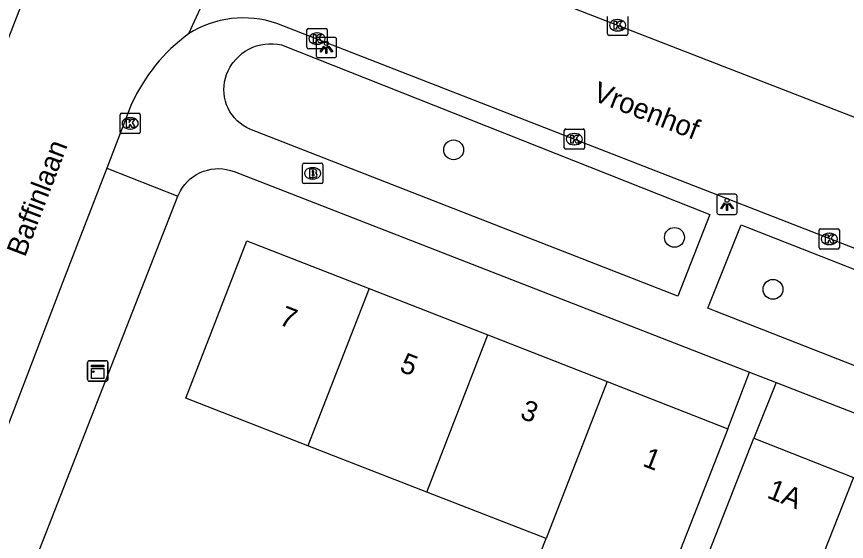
# Model space of a CAD drawing. Extents: x 161253 to 161848, y 384872 to 385383.
# Drawn here: x 161608.6 to 161649.49, y 385097.58 to 385123.42 of the extents above; entities that cross this region are included whole.
import ezdxf

# ---------------------------------------------------------------- set-up
doc = ezdxf.new("R2010")
doc.units = 0
for name, color, linetype in [('IMGEO_Boom', 7, 'Continuous'), ('IMGEO_Brandkraan', 7, 'Continuous'), ('IMGEO_Kast', 7, 'Continuous'), ('IMGEO_Kolk', 7, 'Continuous'), ('IMGEO_Lichtpunt', 7, 'Continuous'), ('IMGEO_Openbare_ruimte_label', 7, 'Continuous'), ('IMGEO_Pand', 7, 'Continuous'), ('IMGEO_Pand_nummerreeks', 7, 'Continuous'), ('IMGEO_Rijbaan_lokaal_open', 7, 'Continuous'), ('IMGEO_Voetpad_open', 7, 'Continuous')]:
    doc.layers.add(name, color=color, linetype=linetype)

msp = doc.modelspace()

# ---------------------------------------------------------------- linework, layer by layer
at = {"layer": 'IMGEO_Boom'}
for centre in [(161630.137, 385116.861), (161641.02, 385112.549), (161645.875, 385109.992)]:
    msp.add_circle(centre, 0.489, dxfattribs=at)
at = {"layer": 'IMGEO_Brandkraan'}
for p, q in [((161622.764, 385116.202), (161623.616, 385116.202)), ((161622.689, 385115.276), (161622.689, 385116.128)), ((161623.177, 385115.982), (161623.202, 385115.982)), ((161623.69, 385116.128), (161623.69, 385115.276)), ((161623.2, 385115.422), (161623.175, 385115.422)), ((161623.616, 385115.202), (161622.764, 385115.202))]:
    msp.add_line(p, q, dxfattribs=at)
for points in [[(161622.764, 385116.202), (161623.616, 385116.202)], [(161622.689, 385115.276), (161622.689, 385116.128)], [(161623.037, 385115.902), (161623.037, 385115.502), (161623.25, 385115.502)], [(161623.268, 385115.902), (161623.037, 385115.902)], [(161623.216, 385115.821), (161623.162, 385115.821), (161623.162, 385115.745)], [(161623.69, 385116.128), (161623.69, 385115.276)], [(161623.162, 385115.745), (161623.215, 385115.745)], [(161623.224, 385115.669), (161623.162, 385115.669), (161623.162, 385115.588)], [(161623.162, 385115.588), (161623.224, 385115.588)], [(161623.616, 385115.202), (161622.764, 385115.202)]]:
    msp.add_lwpolyline(points, dxfattribs=at)
for centre, radius, start, end in [((161622.766, 385116.126), 0.0765, 91.552, 178.448), ((161622.766, 385116.126), 0.0765, 91.552, 178.448), ((161623.614, 385116.126), 0.0765, 1.552, 88.448), ((161623.614, 385116.126), 0.0765, 1.552, 88.448), ((161623.217, 385115.783), 0.0379, 267.8285, 90.9355), ((161623.272, 385115.757), 0.145, 59.4692, 91.5367), ((161623.297, 385115.804), 0.0922, 285.5137, 58.1501), ((161623.225, 385115.628), 0.0404, 269.8759, 90.5077), ((161623.256, 385115.753), 0.251, 268.6676, 293.5347), ((161623.302, 385115.612), 0.105, 301.3115, 78.989), ((161622.766, 385115.278), 0.0765, 181.552, 268.448), ((161622.766, 385115.278), 0.0765, 181.552, 268.448), ((161623.614, 385115.278), 0.0765, 271.552, 358.448), ((161623.614, 385115.278), 0.0765, 271.552, 358.448)]:
    msp.add_arc(centre, radius, start, end, dxfattribs=at)
for centre, major_axis, ratio, start_param, end_param in [((161623.176, 385115.702), (-0.387, 0.002), 0.722429, 4.712389, 7.853982), ((161623.201, 385115.702), (-0.39, 0.002), 0.717154, 1.570796, 4.712389)]:
    msp.add_ellipse(centre, major_axis=major_axis, ratio=ratio, start_param=start_param, end_param=end_param, dxfattribs=at)
at = {"layer": 'IMGEO_Kast'}
for p, q in [((161612.097, 385105.546), (161612.097, 385106.387)), ((161612.097, 385106.387), (161612.097, 385105.546)), ((161612.172, 385106.471), (161613.013, 385106.471)), ((161613.013, 385106.471), (161612.172, 385106.471)), ((161613.097, 385106.396), (161613.097, 385105.555)), ((161613.097, 385105.555), (161613.097, 385106.396)), ((161613.022, 385105.471), (161612.181, 385105.471)), ((161612.181, 385105.471), (161613.022, 385105.471))]:
    msp.add_line(p, q, dxfattribs=at)
for points in [[(161612.292, 385106.261), (161612.892, 385106.261), (161612.892, 385106.176), (161612.292, 385106.176), (161612.292, 385106.261)], [(161612.292, 385106.086), (161612.892, 385106.086), (161612.892, 385105.597), (161612.292, 385105.597), (161612.292, 385106.086)]]:
    msp.add_lwpolyline(points, dxfattribs=at)
msp.add_circle((161612.376, 385105.935), 0.0377, dxfattribs=at)
for centre, start, end in [((161612.175, 385106.393), 92.4484, 184.2845), ((161612.175, 385106.393), 92.4484, 184.2845), ((161613.019, 385106.393), 2.4484, 94.2845), ((161613.019, 385106.393), 2.4484, 94.2845), ((161613.019, 385105.549), 272.4484, 4.2845), ((161613.019, 385105.549), 272.4484, 4.2845), ((161612.175, 385105.549), 182.4484, 274.2845), ((161612.175, 385105.549), 182.4484, 274.2845)]:
    msp.add_arc(centre, 0.0779, start, end, dxfattribs=at)
at = {"layer": 'IMGEO_Kolk'}
for p, q in [((161637.72, 385122.568), (161637.72, 385123.42)), ((161638.208, 385123.274), (161638.233, 385123.274)), ((161638.721, 385123.42), (161638.721, 385122.568)), ((161622.907, 385121.91), (161622.907, 385122.762)), ((161622.982, 385122.836), (161623.834, 385122.836)), ((161623.908, 385122.762), (161623.908, 385121.91)), ((161623.395, 385122.616), (161623.42, 385122.616)), ((161638.647, 385122.494), (161637.795, 385122.494)), ((161638.231, 385122.714), (161638.206, 385122.714)), ((161623.418, 385122.056), (161623.393, 385122.056)), ((161623.834, 385121.836), (161622.982, 385121.836)), ((161613.77, 385118.663), (161614.622, 385118.663)), ((161613.695, 385117.737), (161613.695, 385118.589)), ((161614.183, 385118.443), (161614.208, 385118.443)), ((161614.696, 385118.589), (161614.696, 385117.737)), ((161614.206, 385117.883), (161614.181, 385117.883)), ((161635.662, 385117.886), (161636.514, 385117.886)), ((161614.622, 385117.663), (161613.77, 385117.663)), ((161635.587, 385116.96), (161635.587, 385117.812)), ((161636.075, 385117.666), (161636.1, 385117.666)), ((161636.588, 385117.812), (161636.588, 385116.96)), ((161636.098, 385117.106), (161636.073, 385117.106)), ((161636.514, 385116.886), (161635.662, 385116.886)), ((161648.224, 385112.973), (161649.076, 385112.973)), ((161648.149, 385112.047), (161648.149, 385112.899)), ((161648.637, 385112.753), (161648.662, 385112.753)), ((161649.15, 385112.899), (161649.15, 385112.047)), ((161648.66, 385112.193), (161648.635, 385112.193)), ((161649.076, 385111.973), (161648.224, 385111.973))]:
    msp.add_line(p, q, dxfattribs=at)
for points in [[(161637.72, 385122.568), (161637.72, 385123.42)], [(161638.041, 385123.194), (161638.164, 385123.194), (161638.164, 385123.043), (161638.294, 385123.194), (161638.458, 385123.194), (161638.312, 385123.043), (161638.465, 385122.794), (161638.313, 385122.794), (161638.228, 385122.958), (161638.164, 385122.891), (161638.164, 385122.794), (161638.041, 385122.794), (161638.041, 385123.194)], [(161638.721, 385123.42), (161638.721, 385122.568)], [(161622.907, 385121.91), (161622.907, 385122.762)], [(161622.982, 385122.836), (161623.834, 385122.836)], [(161623.908, 385122.762), (161623.908, 385121.91)], [(161623.228, 385122.536), (161623.351, 385122.536), (161623.351, 385122.385), (161623.481, 385122.536), (161623.645, 385122.536), (161623.499, 385122.385), (161623.652, 385122.136), (161623.5, 385122.136), (161623.415, 385122.3), (161623.351, 385122.233), (161623.351, 385122.136), (161623.228, 385122.136), (161623.228, 385122.536)], [(161638.647, 385122.494), (161637.795, 385122.494)], [(161623.834, 385121.836), (161622.982, 385121.836)], [(161613.77, 385118.663), (161614.622, 385118.663)], [(161613.695, 385117.737), (161613.695, 385118.589)], [(161614.016, 385118.363), (161614.139, 385118.363), (161614.139, 385118.212), (161614.269, 385118.363), (161614.433, 385118.363), (161614.287, 385118.212), (161614.44, 385117.963), (161614.288, 385117.963), (161614.203, 385118.127), (161614.139, 385118.06), (161614.139, 385117.963), (161614.016, 385117.963), (161614.016, 385118.363)], [(161614.696, 385118.589), (161614.696, 385117.737)], [(161635.662, 385117.886), (161636.514, 385117.886)], [(161614.622, 385117.663), (161613.77, 385117.663)], [(161635.587, 385116.96), (161635.587, 385117.812)], [(161635.908, 385117.586), (161636.031, 385117.586), (161636.031, 385117.435), (161636.161, 385117.586), (161636.325, 385117.586), (161636.179, 385117.435), (161636.332, 385117.186), (161636.18, 385117.186), (161636.095, 385117.35), (161636.031, 385117.283), (161636.031, 385117.186), (161635.908, 385117.186), (161635.908, 385117.586)], [(161636.588, 385117.812), (161636.588, 385116.96)], [(161636.514, 385116.886), (161635.662, 385116.886)], [(161648.224, 385112.973), (161649.076, 385112.973)], [(161648.149, 385112.047), (161648.149, 385112.899)], [(161648.47, 385112.673), (161648.593, 385112.673), (161648.593, 385112.522), (161648.723, 385112.673), (161648.887, 385112.673), (161648.741, 385112.522), (161648.894, 385112.273), (161648.742, 385112.273), (161648.657, 385112.437), (161648.593, 385112.37), (161648.593, 385112.273), (161648.47, 385112.273), (161648.47, 385112.673)], [(161649.15, 385112.899), (161649.15, 385112.047)], [(161649.076, 385111.973), (161648.224, 385111.973)]]:
    msp.add_lwpolyline(points, dxfattribs=at)
for centre, start, end in [((161622.984, 385122.76), 91.552, 178.448), ((161622.984, 385122.76), 91.552, 178.448), ((161623.832, 385122.76), 1.552, 88.448), ((161623.832, 385122.76), 1.552, 88.448), ((161637.797, 385122.57), 181.552, 268.448), ((161637.797, 385122.57), 181.552, 268.448), ((161638.645, 385122.57), 271.552, 358.448), ((161638.645, 385122.57), 271.552, 358.448), ((161622.984, 385121.912), 181.552, 268.448), ((161622.984, 385121.912), 181.552, 268.448), ((161623.832, 385121.912), 271.552, 358.448), ((161623.832, 385121.912), 271.552, 358.448), ((161613.772, 385118.587), 91.552, 178.448), ((161613.772, 385118.587), 91.552, 178.448), ((161614.62, 385118.587), 1.552, 88.448), ((161614.62, 385118.587), 1.552, 88.448), ((161635.664, 385117.81), 91.552, 178.448), ((161635.664, 385117.81), 91.552, 178.448), ((161636.512, 385117.81), 1.552, 88.448), ((161636.512, 385117.81), 1.552, 88.448), ((161613.772, 385117.739), 181.552, 268.448), ((161613.772, 385117.739), 181.552, 268.448), ((161614.62, 385117.739), 271.552, 358.448), ((161614.62, 385117.739), 271.552, 358.448), ((161635.664, 385116.962), 181.552, 268.448), ((161635.664, 385116.962), 181.552, 268.448), ((161636.512, 385116.962), 271.552, 358.448), ((161636.512, 385116.962), 271.552, 358.448), ((161648.226, 385112.897), 91.552, 178.448), ((161648.226, 385112.897), 91.552, 178.448), ((161649.074, 385112.897), 1.552, 88.448), ((161649.074, 385112.897), 1.552, 88.448), ((161648.226, 385112.049), 181.552, 268.448), ((161648.226, 385112.049), 181.552, 268.448), ((161649.074, 385112.049), 271.552, 358.448), ((161649.074, 385112.049), 271.552, 358.448)]:
    msp.add_arc(centre, 0.0765, start, end, dxfattribs=at)
for centre, major_axis, ratio, start_param, end_param in [((161638.207, 385122.994), (-0.387, 0.002), 0.722429, 4.712389, 7.853982), ((161638.232, 385122.994), (-0.39, 0.002), 0.717154, 1.570796, 4.712389), ((161623.394, 385122.336), (-0.387, 0.002), 0.722429, 4.712389, 7.853982), ((161623.419, 385122.336), (-0.39, 0.002), 0.717154, 1.570796, 4.712389), ((161614.182, 385118.163), (-0.387, 0.002), 0.722429, 4.712389, 7.853982), ((161614.207, 385118.163), (-0.39, 0.002), 0.717154, 1.570796, 4.712389), ((161636.074, 385117.386), (-0.387, 0.002), 0.722429, 4.712389, 7.853982), ((161636.099, 385117.386), (-0.39, 0.002), 0.717154, 1.570796, 4.712389), ((161648.636, 385112.473), (-0.387, 0.002), 0.722429, 4.712389, 7.853982), ((161648.661, 385112.473), (-0.39, 0.002), 0.717154, 1.570796, 4.712389)]:
    msp.add_ellipse(centre, major_axis=major_axis, ratio=ratio, start_param=start_param, end_param=end_param, dxfattribs=at)
at = {"layer": 'IMGEO_Lichtpunt'}
for p, q in [((161624.269, 385122.398), (161623.461, 385122.398)), ((161624.269, 385122.398), (161623.461, 385122.398)), ((161623.367, 385122.303), (161623.367, 385121.496)), ((161623.367, 385122.303), (161623.367, 385121.496)), ((161624.363, 385121.496), (161624.363, 385122.303)), ((161624.363, 385121.496), (161624.363, 385122.303)), ((161623.461, 385121.402), (161624.269, 385121.402)), ((161623.461, 385121.402), (161624.269, 385121.402)), ((161643.112, 385114.579), (161643.112, 385113.772)), ((161643.112, 385114.579), (161643.112, 385113.772)), ((161644.014, 385114.674), (161643.206, 385114.674)), ((161644.014, 385114.674), (161643.206, 385114.674)), ((161644.108, 385113.772), (161644.108, 385114.579)), ((161644.108, 385113.772), (161644.108, 385114.579)), ((161643.206, 385113.678), (161644.014, 385113.678)), ((161643.206, 385113.678), (161644.014, 385113.678))]:
    msp.add_line(p, q, dxfattribs=at)
for points in [[(161623.741, 385121.967), (161623.78, 385121.939), (161623.592, 385121.677), (161623.554, 385121.704), (161623.741, 385121.967)], [(161623.843, 385121.919), (161623.89, 385121.919), (161623.89, 385121.597), (161623.843, 385121.597), (161623.843, 385121.919)], [(161623.953, 385121.939), (161623.991, 385121.966), (161624.178, 385121.704), (161624.139, 385121.676), (161623.953, 385121.939)], [(161643.486, 385114.243), (161643.525, 385114.215), (161643.337, 385113.953), (161643.299, 385113.98), (161643.486, 385114.243)], [(161643.588, 385114.195), (161643.635, 385114.195), (161643.635, 385113.873), (161643.588, 385113.873), (161643.588, 385114.195)], [(161643.698, 385114.215), (161643.736, 385114.242), (161643.923, 385113.98), (161643.884, 385113.952), (161643.698, 385114.215)]]:
    msp.add_lwpolyline(points, dxfattribs=at)
for centre in [(161623.866, 385122.101), (161643.611, 385114.377)]:
    msp.add_circle(centre, 0.0994, dxfattribs=at)
for centre, start, end in [((161623.461, 385122.303), 90, 180), ((161623.461, 385122.303), 90, 180), ((161624.269, 385122.303), 0, 90), ((161624.269, 385122.303), 0, 90), ((161623.461, 385121.496), 180, 270), ((161623.461, 385121.496), 180, 270), ((161624.269, 385121.496), 270, 0), ((161624.269, 385121.496), 270, 360), ((161643.206, 385114.579), 90, 180), ((161643.206, 385114.579), 90, 180), ((161644.014, 385114.579), 0, 90), ((161644.014, 385114.579), 0, 90), ((161643.206, 385113.772), 180, 270), ((161643.206, 385113.772), 180, 270), ((161644.014, 385113.772), 270, 0), ((161644.014, 385113.772), 270, 360)]:
    msp.add_arc(centre, 0.0946, start, end, dxfattribs=at)
at = {"layer": 'IMGEO_Pand'}
for points in [[(161622.948, 385102.294), (161616.939, 385104.629), (161619.952, 385112.383), (161625.973, 385110.031)], [(161625.973, 385110.031), (161622.948, 385102.294)], [(161625.973, 385110.031), (161631.817, 385107.748)], [(161628.823, 385100.011), (161631.817, 385107.748)], [(161631.817, 385107.748), (161637.698, 385105.451)], [(161637.698, 385105.451), (161634.689, 385097.731)], [(161637.698, 385105.451), (161643.642, 385103.129)], [(161643.642, 385103.129), (161640.622, 385095.425), (161639.51, 385092.589)], [(161628.823, 385100.011), (161622.948, 385102.294)], [(161642.238, 385095.704), (161642.197, 385095.72), (161642.887, 385097.469), (161644.937, 385102.67)], [(161644.937, 385102.67), (161649.844, 385100.733)], [(161649.844, 385100.733), (161647.102, 385093.79)], [(161634.689, 385097.731), (161628.823, 385100.011)], [(161639.51, 385092.589), (161633.583, 385094.893), (161634.689, 385097.731)]]:
    msp.add_lwpolyline(points, dxfattribs=at)
at = {"layer": 'IMGEO_Rijbaan_lokaal_open'}
for points in [[(161621.309, 385131.792), (161617.068, 385122.566)], [(161665.69, 385112.325), (161625.181, 385128.058), (161624.4, 385128.348)], [(161594.264, 385086.477), (161601.214, 385104.169), (161608.098, 385122.102), (161609.658, 385126.137)], [(161664.299, 385106.388), (161663.998, 385106.512), (161659.112, 385108.427), (161621.419, 385123.084)], [(161614.264, 385119.122), (161613.044, 385115.957)], [(161613.044, 385115.957), (161610.967, 385110.567), (161606.772, 385099.678), (161603.558, 385091.164), (161600.836, 385084.252), (161600.202, 385082.833), (161599.431, 385081.45)]]:
    msp.add_lwpolyline(points, dxfattribs=at)
for centre, radius, start, end in [((161619.781, 385118.309), 5.048, 71.0665, 122.5121), ((161622.314, 385115.431), 8.856, 126.3265, 155.3707)]:
    msp.add_arc(centre, radius, start, end, dxfattribs=at)
at = {"layer": 'IMGEO_Voetpad_open'}
for points in [[(161641.19, 385109.659), (161620.1, 385117.875), (161619.928, 385117.957), (161619.765, 385118.055), (161619.612, 385118.167), (161619.468, 385118.292), (161619.337, 385118.43), (161619.218, 385118.579), (161619.114, 385118.737), (161619.024, 385118.905), (161618.949, 385119.079), (161618.89, 385119.26), (161618.847, 385119.446), (161618.821, 385119.634), (161618.812, 385119.824), (161618.82, 385120.014), (161618.845, 385120.202), (161618.887, 385120.388), (161618.945, 385120.569), (161619.019, 385120.744), (161619.109, 385120.912), (161619.213, 385121.071), (161619.271, 385121.154), (161619.402, 385121.314), (161619.546, 385121.462), (161619.702, 385121.596), (161619.87, 385121.716), (161620.048, 385121.82), (161620.235, 385121.908), (161620.429, 385121.979), (161620.628, 385122.033), (161620.832, 385122.068), (161621.037, 385122.085), (161621.244, 385122.084), (161621.449, 385122.064), (161621.652, 385122.026), (161642.755, 385113.676), (161641.19, 385109.659)], [(161613.044, 385115.957), (161616.549, 385114.582)], [(161616.549, 385114.582), (161616.587, 385114.671), (161616.673, 385114.842), (161616.774, 385115.005), (161616.889, 385115.158), (161617.017, 385115.3), (161617.157, 385115.43), (161617.309, 385115.547), (161617.47, 385115.65), (161617.64, 385115.738), (161617.817, 385115.81), (161618, 385115.867), (161618.187, 385115.907), (161618.377, 385115.93), (161618.568, 385115.936), (161618.759, 385115.925), (161618.949, 385115.896), (161619.135, 385115.851), (161619.316, 385115.79), (161644.724, 385105.911)], [(161609.588, 385096.835), (161616.549, 385114.582)], [(161665.67, 385102.291), (161665.654, 385102.248), (161665.58, 385102.081), (161665.493, 385101.922), (161665.391, 385101.771), (161665.276, 385101.63), (161665.149, 385101.5), (161665.011, 385101.382), (161664.863, 385101.276), (161664.706, 385101.184), (161664.541, 385101.107), (161664.371, 385101.044), (161664.195, 385100.997), (161664.016, 385100.966), (161663.834, 385100.951), (161663.653, 385100.953), (161663.472, 385100.97), (161663.293, 385101.004), (161663.118, 385101.053), (161662.948, 385101.118), (161643.083, 385108.902), (161642.671, 385109.067), (161644.312, 385113.168)], [(161644.312, 385113.168), (161644.724, 385113.003), (161664.27, 385105.333)], [(161643.642, 385103.129), (161644.724, 385105.911)], [(161644.724, 385105.911), (161646.03, 385105.403)], [(161646.03, 385105.403), (161644.937, 385102.67)], [(161646.03, 385105.403), (161664.489, 385098.225)]]:
    msp.add_lwpolyline(points, dxfattribs=at)

# ---------------------------------------------------------------- texts
at = {"layer": 'IMGEO_Openbare_ruimte_label'}
for s, rotation, p in [('Vroenhof', 338.6456, (161636.939, 385119.317)), ('Baffinlaan', 69.1353, (161609.011, 385111.54))]:
    msp.add_text(s, height=1, rotation=rotation, dxfattribs=at).set_placement(p)
at = {"layer": 'IMGEO_Pand_nummerreeks'}
for s, rotation, p in [('7', 338.7643, (161621.48, 385108.278)), ('5', 338.7643, (161627.419, 385105.97)), ('3', 338.7643, (161633.357, 385103.663)), ('1', 338.7662, (161639.402, 385101.315)), ('1A', 338.4568, (161645.526, 385099.75))]:
    msp.add_text(s, height=1, rotation=rotation, dxfattribs=at).set_placement(p)

doc.saveas('drawing.dxf')
